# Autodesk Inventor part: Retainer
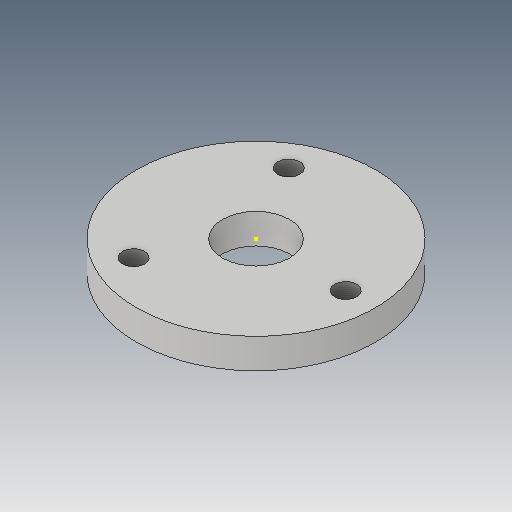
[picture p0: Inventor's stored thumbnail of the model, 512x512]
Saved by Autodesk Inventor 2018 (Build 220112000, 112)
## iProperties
Created: 2016-05
Part Number: Retainer
Material: Generic
Document SubType Name: Modeling
Designer: CADCIM
Density: 1 g/cm^3
Appearance: Default
Author: CADCIM
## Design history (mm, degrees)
sketch "Sketch1"
  geometry: C1 r 100 at (0, 0); 1 further point
  constraints: 1 centre point, 1 coincident
  dimensions: "d0" = 200 diameter of C1
extrude "Extrusion1" new body sketch "Sketch1" distance "d1" = 25; taper "d2" = 0 deg
sketch "Sketch2"
  geometry: 1 further point
sketch "Sketch3" dims "d3" = 150
  geometry: L1 (0, 0)-(102.916, 0); 2 further points
  constraints: 2 end point, 1 coincident, 1 horizontal, 1 horizontal alignment, 1 point on line, 2 other
hole "Hole1" sketch "Sketch3" at (75, 0) diameter "d4" = 18.376; stored, may be unused: countersink angle "d8" = 90 deg, drill point angle "d10" = 118 deg; dims "d5" = 40, "d6" = 4, "d7" = 2, "d9" = 47.3
pattern_circular "Circular Pattern1" dims angle "d12" = 360 deg
sketch "Sketch4"
  geometry: C1 r 28 at (0, 0); 1 further point
  constraints: 1 centre point, 1 coincident
  dimensions: "d14" = 56 diameter of C1
extrude "Extrusion2" cut sketch "Sketch4" distance "d15" = 25; taper "d16" = 0 deg
body "Solid1"
